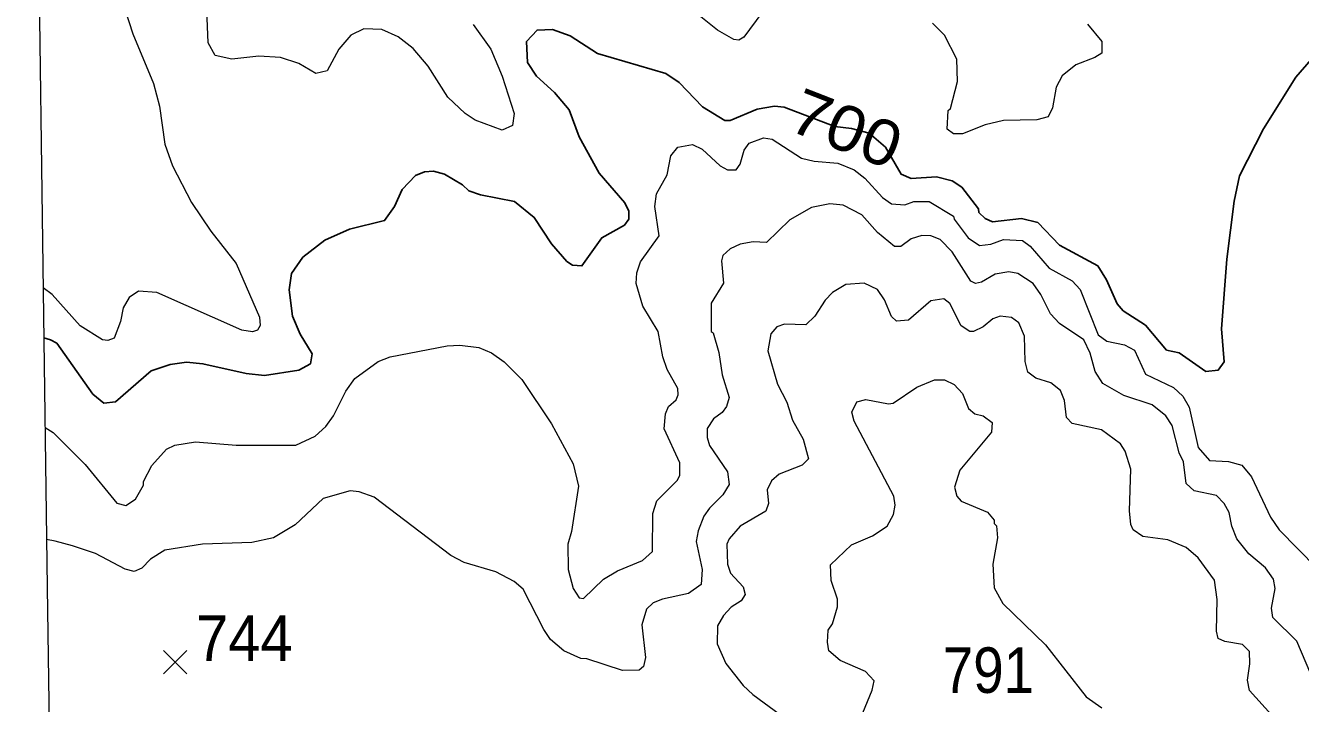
# Model space of a CAD drawing. Extents: x 265 to 291.4, y 7731.5 to 7759.6.
# Drawn here: x 264.956 to 267.199, y 7756.199 to 7757.39 of the extents above; entities that cross this region are included whole.
import ezdxf
from ezdxf.enums import TextEntityAlignment as Align

# ---------------------------------------------------------------- set-up
doc = ezdxf.new("R2010")
doc.units = 0
doc.header["$LTSCALE"] = 0.032
for name, color, linetype, lineweight in [('1', 7, 'Continuous', 25), ('2', 7, 'Continuous', 13), ('21', 7, 'Continuous', 25), ('61', 7, 'Continuous', 13), ('63', 7, 'Continuous', 25)]:
    doc.layers.add(name, color=color, linetype=linetype, lineweight=lineweight)

msp = doc.modelspace()

# ---------------------------------------------------------------- linework, layer by layer
at = {"layer": '1'}
for points in [[(266.633, 7757.0616), (266.6322, 7757.068), (266.6028, 7757.1062), (266.5861, 7757.1173), (266.5583, 7757.1244), (266.5137, 7757.1213), (266.4962, 7757.1292), (266.4684, 7757.1762), (266.4402, 7757.2008), (266.4091, 7757.2094), (266.3793, 7757.2127), (266.2906, 7757.2465), (266.2735, 7757.2485), (266.2432, 7757.243), (266.1955, 7757.2231), (266.186, 7757.2231), (266.147, 7757.247), (266.1056, 7757.2899), (266.0825, 7757.3058), (265.9624, 7757.3408), (265.9139, 7757.3718), (265.8829, 7757.383), (265.8558, 7757.3822), (265.8375, 7757.3623), (265.8391, 7757.3249), (265.855, 7757.3011), (265.8868, 7757.2724), (265.9123, 7757.2422), (265.9298, 7757.1945), (265.9648, 7757.1308), (266.0101, 7757.0783), (266.0173, 7757.064), (266.0173, 7757.0497), (266.0094, 7757.0393), (265.9696, 7757.0171), (265.9346, 7756.9677), (265.9179, 7756.9693), (265.9083, 7756.9757), (265.8813, 7757.0067), (265.851, 7757.0529), (265.816, 7757.0807), (265.7564, 7757.0926), (265.7357, 7757.0998), (265.7246, 7757.1101), (265.6928, 7757.1292), (265.6737, 7757.134), (265.6578, 7757.1332), (265.6419, 7757.1268), (265.6188, 7757.1022), (265.6052, 7757.072), (265.5877, 7757.0473), (265.5257, 7757.0322), (265.4828, 7757.0131), (265.4438, 7756.9829), (265.4239, 7756.9542), (265.4199, 7756.9256), (265.4255, 7756.8795), (265.439, 7756.8476), (265.4605, 7756.8134), (265.4573, 7756.7959), (265.4366, 7756.7848), (265.3762, 7756.7752), (265.3443, 7756.7784), (265.268, 7756.7959), (265.2393, 7756.7983), (265.2107, 7756.7943), (265.1773, 7756.7832), (265.1144, 7756.7291), (265.0938, 7756.7267), (265.0747, 7756.7426), (265.011, 7756.8317), (265.0002, 7756.8377), (264.9885, 7756.8414)], [(267.2368, 7757.3528), (267.1906, 7757.2995), (267.1334, 7757.2088), (267.0912, 7757.1261), (267.0817, 7757.0815), (267.0689, 7756.9797), (267.0594, 7756.8572), (267.0642, 7756.7991), (267.0538, 7756.7848), (267.0323, 7756.7824), (266.9854, 7756.815), (266.9631, 7756.8198), (266.9257, 7756.8635), (266.8868, 7756.889), (266.8764, 7756.9009), (266.8573, 7756.9431), (266.8422, 7756.9678)], [(266.8422, 7756.9678), (266.7746, 7757.0043), (266.7364, 7757.0441), (266.7078, 7757.0513), (266.6569, 7757.0449), (266.6442, 7757.0513), (266.633, 7757.0616)]]:
    msp.add_lwpolyline(points, dxfattribs=at)
at = {"layer": '2'}
for points in [[(265.1248, 7757.4379), (265.1447, 7757.3758), (265.1813, 7757.2883), (265.1916, 7757.2486), (265.2011, 7757.1817)], [(265.7437, 7757.3917), (265.7747, 7757.3488), (265.7946, 7757.3011), (265.8153, 7757.2358), (265.8129, 7757.2143), (265.7946, 7757.2064), (265.7469, 7757.2239), (265.7294, 7757.2358), (265.6991, 7757.2645), (265.6641, 7757.3186), (265.6379, 7757.3496), (265.6116, 7757.3703), (265.583, 7757.383), (265.5512, 7757.3846), (265.5281, 7757.3734), (265.5074, 7757.3488), (265.4867, 7757.3106), (265.4668, 7757.3058), (265.4366, 7757.3233), (265.4048, 7757.3337), (265.3666, 7757.3361), (265.3189, 7757.3313), (265.2895, 7757.3377), (265.2775, 7757.3599), (265.2743, 7757.4315)], [(266.2512, 7757.4124), (266.2194, 7757.3695), (266.2106, 7757.3647), (266.2019, 7757.3655), (266.1732, 7757.3822), (266.1263, 7757.4196)], [(266.8239, 7757.3925), (266.8494, 7757.3623), (266.8494, 7757.3416), (266.8367, 7757.3337), (266.8033, 7757.3209), (266.7794, 7757.3019), (266.769, 7757.282), (266.7627, 7757.2454), (266.7547, 7757.2295), (266.7349, 7757.2247), (266.676, 7757.2231), (266.6442, 7757.2159), (266.6044, 7757.2), (266.5885, 7757.2), (266.5773, 7757.208), (266.5789, 7757.2406), (266.5829, 7757.2446), (266.5956, 7757.2915), (266.594, 7757.3313), (266.5725, 7757.3734), (266.5511, 7757.3941)], [(264.9906, 7756.6836), (265.0047, 7756.675), (265.0611, 7756.6185), (265.1168, 7756.5509), (265.1327, 7756.5469), (265.1494, 7756.5581), (265.1638, 7756.5827), (265.1638, 7756.5891), (265.1781, 7756.617), (265.2043, 7756.6456), (265.2187, 7756.6527), (265.2552, 7756.6583), (265.3268, 7756.6527), (265.4318, 7756.6527), (265.4653, 7756.6686), (265.4843, 7756.6853), (265.4979, 7756.7045), (265.5193, 7756.7474), (265.5352, 7756.7697), (265.5766, 7756.7999), (265.5973, 7756.8079), (265.6975, 7756.827), (265.7198, 7756.8285), (265.7532, 7756.8246), (265.7755, 7756.815), (265.7978, 7756.7991), (265.8288, 7756.7681), (265.8813, 7756.6901), (265.9195, 7756.6201), (265.929, 7756.5804), (265.9163, 7756.5008), (265.9099, 7756.4785), (265.9107, 7756.434), (265.9195, 7756.4006), (265.9298, 7756.3847), (265.9378, 7756.3831), (265.9728, 7756.4173), (265.9974, 7756.4316), (266.0412, 7756.4499), (266.0587, 7756.4658), (266.0595, 7756.5326), (266.0666, 7756.5549), (266.1024, 7756.5907), (266.1072, 7756.5995), (266.1072, 7756.6217), (266.0794, 7756.6814), (266.0817, 7756.7076), (266.0873, 7756.7204), (266.1008, 7756.7323), (266.104, 7756.741), (266.1032, 7756.7522), (266.0849, 7756.7856), (266.077, 7756.8079), (266.069, 7756.8524), (266.042, 7756.897), (266.03, 7756.9367), (266.0316, 7756.9558), (266.038, 7756.9749), (266.0706, 7757.0203), (266.0627, 7757.072), (266.0658, 7757.0942), (266.0849, 7757.1277), (266.0913, 7757.1611), (266.1032, 7757.1762), (266.1295, 7757.1809), (266.1462, 7757.173), (266.178, 7757.1436), (266.1907, 7757.1364), (266.2058, 7757.1364), (266.213, 7757.1467), (266.2202, 7757.1714), (266.2289, 7757.1833), (266.2544, 7757.1929), (266.2695, 7757.1905), (266.3212, 7757.1571), (266.3435, 7757.1515), (266.3848, 7757.1483), (266.4135, 7757.1364), (266.4326, 7757.1221), (266.4636, 7757.0879), (266.4795, 7757.0767), (266.5026, 7757.0751), (266.5185, 7757.0807), (266.5455, 7757.0807), (266.5885, 7757.0553), (266.5893, 7757.0497), (266.6139, 7757.0171), (266.6338, 7757.0036), (266.6537, 7757.0059), (266.676, 7757.0139), (266.7094, 7757.0123), (266.7229, 7757.0027), (266.7563, 7756.9638), (266.7969, 7756.9415), (266.8112, 7756.9264)], [(265.2011, 7757.1817), (265.2147, 7757.1436), (265.2481, 7757.0791), (265.2823, 7757.029), (265.3268, 7756.9717), (265.3674, 7756.8779), (265.369, 7756.8628)], [(266.3944, 7757.0743), (266.3705, 7757.0767), (266.3387, 7757.0704), (266.3005, 7757.0489), (266.2592, 7757.0091), (266.2361, 7757.0099), (266.213, 7757.0059), (266.1955, 7756.998), (266.1828, 7756.9861), (266.1804, 7756.9765), (266.1836, 7756.9375), (266.1621, 7756.9025), (266.1621, 7756.8524), (266.1653, 7756.85), (266.1756, 7756.8158), (266.1812, 7756.7761), (266.1939, 7756.7363), (266.1891, 7756.7204), (266.1812, 7756.71), (266.1661, 7756.6989), (266.1549, 7756.6822), (266.1549, 7756.6663), (266.1589, 7756.6519), (266.1907, 7756.6058), (266.1939, 7756.5835), (266.1828, 7756.5652), (266.1589, 7756.5422), (266.1494, 7756.5279), (266.139, 7756.5024), (266.1358, 7756.4833), (266.1462, 7756.434), (266.1446, 7756.4077), (266.1223, 7756.3918), (266.0762, 7756.3823), (266.0603, 7756.3759), (266.0483, 7756.3648), (266.0404, 7756.3369), (266.0467, 7756.2797), (266.0428, 7756.2638), (266.0356, 7756.2574), (266.0062, 7756.2566), (265.9433, 7756.2773), (265.933, 7756.2781), (265.9028, 7756.2916), (265.8797, 7756.3115), (265.8678, 7756.329), (265.8312, 7756.3998), (265.8153, 7756.4133), (265.7835, 7756.43), (265.7278, 7756.4467), (265.7039, 7756.4586), (265.5695, 7756.5613), (265.5432, 7756.5708), (265.5273, 7756.5724), (265.4796, 7756.5589), (265.4303, 7756.5127), (265.3921, 7756.4897), (265.3539, 7756.4817), (265.2672, 7756.4785), (265.2012, 7756.4682), (265.1758, 7756.4523), (265.1606, 7756.4364), (265.1471, 7756.4308), (265.1312, 7756.4348), (265.0794, 7756.4626), (265.0389, 7756.4761), (265.0081, 7756.4839), (264.9933, 7756.4868)], [(266.5328, 7757.021), (266.5137, 7757.0155), (266.4954, 7757.002), (266.4843, 7757.002), (266.4548, 7757.0266), (266.427, 7757.0577), (266.3944, 7757.0743)], [(267.2169, 7756.2502), (267.1922, 7756.3083), (267.1501, 7756.3497), (267.1477, 7756.3664), (267.1541, 7756.4006), (267.1509, 7756.4173), (267.1373, 7756.4372), (267.1079, 7756.4618), (267.0864, 7756.4881), (267.0777, 7756.5104), (267.0729, 7756.5342), (267.0642, 7756.5501), (267.0506, 7756.5644), (267.0117, 7756.5724), (266.9974, 7756.5851), (266.9926, 7756.6233), (266.9854, 7756.6392), (266.9727, 7756.687), (266.9615, 7756.7045), (266.9377, 7756.7235), (266.8876, 7756.7402), (266.851, 7756.7609), (266.8375, 7756.7824), (266.8287, 7756.8142), (266.8176, 7756.8381), (266.7746, 7756.8667), (266.7587, 7756.8834), (266.742, 7756.9176), (266.7285, 7756.9367), (266.7014, 7756.9542), (266.6855, 7756.9574), (266.6617, 7756.9534), (266.6378, 7756.9391), (266.6267, 7756.9367), (266.6187, 7756.9407), (266.5861, 7756.9924), (266.5646, 7757.0139), (266.5487, 7757.0203), (266.5328, 7757.021)], [(265.369, 7756.8628), (265.3642, 7756.8548), (265.3555, 7756.8516), (265.3364, 7756.8548), (265.1868, 7756.9208), (265.155, 7756.9232), (265.1383, 7756.9121), (265.128, 7756.8938), (265.1232, 7756.8699), (265.112, 7756.8405), (265.1009, 7756.8365), (265.0914, 7756.8381), (265.0524, 7756.8627), (265.0031, 7756.9176), (264.9873, 7756.929)], [(267.1477, 7756.1786), (267.1087, 7756.2216), (267.1055, 7756.2399), (267.1095, 7756.2685), (267.1087, 7756.29), (267.0968, 7756.3027), (267.0658, 7756.3075), (267.0538, 7756.3131), (267.0506, 7756.3258), (267.0522, 7756.3815), (267.0475, 7756.4157), (267.0188, 7756.4547), (266.9974, 7756.473), (266.9655, 7756.4865), (266.921, 7756.492), (266.9043, 7756.504), (266.9003, 7756.5135), (266.8979, 7756.5374), (266.9003, 7756.6106), (266.89, 7756.6424), (266.882, 7756.6551), (266.8486, 7756.6798), (266.7969, 7756.6909), (266.7873, 7756.7013), (266.7834, 7756.7315), (266.7762, 7756.749), (266.7595, 7756.7625), (266.7333, 7756.7705), (266.7189, 7756.7808), (266.7142, 7756.7999), (266.7134, 7756.8445), (266.703, 7756.8675), (266.6903, 7756.8771), (266.6704, 7756.8795), (266.6577, 7756.8747), (266.6402, 7756.8604), (266.6235, 7756.8524), (266.6171, 7756.8524), (266.602, 7756.8627), (266.5821, 7756.9017), (266.571, 7756.9097), (266.5487, 7756.9065), (266.5089, 7756.8723), (266.4882, 7756.8707), (266.4795, 7756.8786), (266.4668, 7756.9081), (266.4548, 7756.9264), (266.431, 7756.9375), (266.3992, 7756.9351), (266.3753, 7756.9208), (266.3626, 7756.9073), (266.3443, 7756.8795), (266.3283, 7756.8643), (266.291, 7756.8651), (266.2774, 7756.8604), (266.2671, 7756.8484), (266.2615, 7756.8182), (266.279, 7756.7601), (266.2949, 7756.7283), (266.3053, 7756.6965), (266.3236, 7756.6631), (266.3331, 7756.6289), (266.322, 7756.6177), (266.2814, 7756.6018), (266.2679, 7756.5899), (266.2607, 7756.574), (266.2631, 7756.5501), (266.2583, 7756.5366), (266.213, 7756.5104), (266.1939, 7756.4881), (266.1899, 7756.4785), (266.1907, 7756.4435), (266.1963, 7756.4276), (266.2186, 7756.4038), (266.2217, 7756.3902), (266.2146, 7756.3791), (266.1971, 7756.368), (266.1836, 7756.3536), (266.1732, 7756.3353), (266.1724, 7756.3035), (266.1876, 7756.2693), (266.2186, 7756.2303), (266.2353, 7756.2144), (266.2838, 7756.1786)], [(266.8112, 7756.9264), (266.843, 7756.8468), (266.8581, 7756.8357), (266.8892, 7756.8293), (266.9067, 7756.8198), (266.9257, 7756.7776), (266.9751, 7756.7538)], [(266.4286, 7756.1826), (266.4453, 7756.2224), (266.4485, 7756.2383), (266.4333, 7756.255), (266.3888, 7756.2741), (266.3689, 7756.2916), (266.3665, 7756.3067), (266.3681, 7756.3274), (266.3753, 7756.3385), (266.384, 7756.3688), (266.384, 7756.3823), (266.3729, 7756.4149), (266.3721, 7756.4427), (266.4087, 7756.4777), (266.4461, 7756.4936), (266.4715, 7756.5104), (266.4827, 7756.531), (266.4859, 7756.547), (266.4835, 7756.5629), (266.4135, 7756.6949), (266.4095, 7756.7108), (266.4182, 7756.7291), (266.4342, 7756.7331), (266.4739, 7756.7251), (266.4819, 7756.7267), (266.524, 7756.7546), (266.5551, 7756.7673), (266.5726, 7756.7673), (266.5893, 7756.7593), (266.6044, 7756.7434), (266.6147, 7756.7172), (266.6259, 7756.7076), (266.6402, 7756.7044), (266.6561, 7756.6925), (266.6553, 7756.6758), (266.5996, 7756.609), (266.5901, 7756.5788), (266.594, 7756.5629), (266.602, 7756.5541), (266.6481, 7756.535), (266.6601, 7756.5207), (266.6601, 7756.5151), (266.664, 7756.5111), (266.6656, 7756.4897)], [(266.9751, 7756.7538), (266.9918, 7756.7386), (267.0029, 7756.7196), (267.0188, 7756.6488), (267.0387, 7756.6257), (267.0721, 7756.6241), (267.0952, 7756.6177), (267.1127, 7756.5971), (267.1461, 7756.5263), (267.1612, 7756.504), (267.2273, 7756.4364), (267.2328, 7756.4054), (267.2257, 7756.3608), (267.2567, 7756.3298), (267.2615, 7756.3115), (267.2702, 7756.2971), (267.2758, 7756.2932), (267.2981, 7756.2892), (267.3458, 7756.2932), (267.3871, 7756.29), (267.4094, 7756.2844), (267.4874, 7756.2518), (267.5287, 7756.2279), (267.6194, 7756.1595)], [(266.6656, 7756.4897), (266.6577, 7756.4435), (266.6601, 7756.4022), (266.6752, 7756.3743), (266.75, 7756.3019), (266.8215, 7756.2105), (266.8494, 7756.1914)]]:
    msp.add_lwpolyline(points, dxfattribs=at)
at = {"layer": '21'}
for p, q in [((265.1986, 7756.2919), (265.2398, 7756.2507)), ((265.2398, 7756.2919), (265.1986, 7756.2507))]:
    msp.add_line(p, q, dxfattribs=at)
at = {"layer": '63', "lineweight": 13}
msp.add_lwpolyline([(264.9561, 7759.2271), (264.9638, 7758.6622), (264.9715, 7758.0972), (264.9791, 7757.5323), (264.9868, 7756.9673), (264.9945, 7756.4024), (265.0022, 7755.8374), (265.0099, 7755.2725), (265.0176, 7754.7075), (265.0253, 7754.1426), (265.033, 7753.5776), (265.0407, 7753.0126), (265.0484, 7752.4477), (265.0561, 7751.8827), (265.0638, 7751.3178), (265.0715, 7750.7528), (265.0793, 7750.1879), (265.087, 7749.6229), (265.0947, 7749.058), (265.1024, 7748.493), (265.1101, 7747.9281), (265.1178, 7747.3631), (265.1256, 7746.7981), (265.1333, 7746.2332)], dxfattribs=at)

# ---------------------------------------------------------------- texts
at = {"layer": '61', "width": 1.1}
msp.add_text('700', height=0.08, rotation=338.718, dxfattribs=at).set_placement((266.3856, 7757.1719), align=Align.CENTER)
at = {"layer": '61'}
for s, width, p in [('744', 0.95, (265.341, 7756.2737)), ('791', 0.9, (266.6497, 7756.2174))]:
    msp.add_text(s, height=0.08, dxfattribs=dict(at, width=width)).set_placement(p, align=Align.CENTER)

doc.saveas('drawing.dxf')
